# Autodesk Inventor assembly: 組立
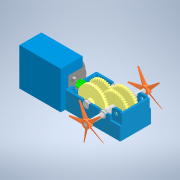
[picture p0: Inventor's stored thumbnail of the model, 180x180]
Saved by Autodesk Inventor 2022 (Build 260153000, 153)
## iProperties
Created: 2024-12
Part Number: 組立
Document SubType Name: Assembly
Designer: jsat7
Author: jsat7
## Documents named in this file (17)
- C:\Users\jsat7\OneDrive\デスクトップ\卒論2024\３DCAD\自在ギヤボックス\組立図\組立　低速.iam
- C:\Users\jsat7\OneDrive\デスクトップ\卒論2024\３DCAD\自在ギヤボックス\部品図\ボックス　下.ipt
- C:\Users\jsat7\OneDrive\デスクトップ\卒論2024\３DCAD\自在ギヤボックス\部品図\B3.ipt
- C:\Users\jsat7\OneDrive\デスクトップ\卒論2024\３DCAD\自在ギヤボックス\部品図\2段平ギア.iam
- C:\Users\jsat7\OneDrive\デスクトップ\卒論2024\３DCAD\自在ギヤボックス\部品図\B4.ipt
- C:\Users\jsat7\OneDrive\デスクトップ\卒論2024\３DCAD\自在ギヤボックス\部品図\B6.ipt
- C:\Users\jsat7\OneDrive\デスクトップ\卒論2024\３DCAD\自在ギヤボックス\部品図\丸棒.ipt
- C:\Users\jsat7\OneDrive\デスクトップ\卒論2024\３DCAD\自在ギヤボックス\部品図\クラウンギア.iam
- C:\Users\jsat7\OneDrive\デスクトップ\卒論2024\３DCAD\自在ギヤボックス\部品図\モーター　ピニオンギア.iam
- C:\Users\jsat7\OneDrive\デスクトップ\卒論2024\３DCAD\自在ギヤボックス\部品図\モーター　箱.ipt
- C:\Users\jsat7\OneDrive\デスクトップ\卒論2024\３DCAD\自在ギヤボックス\部品図\ピニオンギア.ipt
- C:\Users\jsat7\OneDrive\デスクトップ\卒論2024\３DCAD\自在ギヤボックス\部品図\特殊平ギア.ipt
- C:\Users\jsat7\OneDrive\デスクトップ\卒論2024\３DCAD\自在ギヤボックス\部品図\六角シャフト.ipt
- C:\Users\jsat7\OneDrive\デスクトップ\卒論2024\３DCAD\自在ギヤボックス\部品図\固定器具.ipt
- C:\Users\jsat7\OneDrive\デスクトップ\卒論2024\３DCAD\自在ギヤボックス\部品図\B7.ipt
- C:\Users\jsat7\OneDrive\デスクトップ\卒論2024\３DCAD\自在ギヤボックス\部品図\ボックス　上.ipt
- C:\Users\jsat7\OneDrive\デスクトップ\卒論2024\３DCAD\自在ギヤボックス\部品図\プロペラ.ipt
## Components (15 placed, 12 different names)
1. B4:1 — メイト:2, フラッシュ:2, メイト:3
2. B6:1 — メイト:1, メイト:28, メイト:29, フラッシュ:13
3. 丸棒:1 — メイト:3, メイト:5, メイト:20, メイト:28
4. クラウンギア:1 [sub-assembly] — メイト:5, メイト:22, 回転:1, 回転:2, メイト:29
5. モーター　ピニオンギア:1 [sub-assembly] — フラッシュ:5, フラッシュ:6, メイト:13, メイト:14, フラッシュ:8
6. 平歯車1:1 — メイト:14, フラッシュ:8, 回転:1, 角度:1
7. 平歯車1:2 — リジッド:1, メイト:23, 回転:4
8. 六角シャフト:1 — リジッド:1, リジッド:2, メイト:21, メイト:26, リジッド:3, リジッド:4
9. 固定器具:1 — リジッド:2, メイト:27
10. 2段平ギア:1 [sub-assembly] — メイト:20, メイト:22, 回転:3, 回転:4
11. 2段平ギア:2 [sub-assembly] — メイト:21, メイト:23, 回転:2, 回転:3
12. B3:1 — メイト:24, フラッシュ:11
13. B7:1 — メイト:25, フラッシュ:12, メイト:26, メイト:27
14. プロペラ:1 — リジッド:3
15. プロペラ:2 — リジッド:4
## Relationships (32: Mate 16, Flush 7, WeldJoint 4, RelateRotation 4, Angle 1)
- メイト:1 [Mate]: B6:1
- メイト:2 [Mate]: B4:1
- フラッシュ:2 [Flush]: B4:1
- メイト:3 [Mate]: B4:1 ↔ 丸棒:1
- メイト:5 [Mate]: 丸棒:1 ↔ クラウンギア:1
- フラッシュ:5 [Flush]: モーター　ピニオンギア:1
- フラッシュ:6 [Flush]: モーター　ピニオンギア:1
- メイト:13 [Mate]: モーター　ピニオンギア:1
- メイト:14 [Mate]: モーター　ピニオンギア:1 ↔ 平歯車1:1
- フラッシュ:8 [Flush]: モーター　ピニオンギア:1 ↔ 平歯車1:1
- リジッド:1 [WeldJoint]: 平歯車1:2 ↔ 六角シャフト:1
- リジッド:2 [WeldJoint]: 六角シャフト:1 ↔ 固定器具:1
- メイト:20 [Mate]: 丸棒:1 ↔ 2段平ギア:1
- メイト:21 [Mate]: 六角シャフト:1 ↔ 2段平ギア:2
- メイト:22 [Mate]: クラウンギア:1 ↔ 2段平ギア:1
- メイト:23 [Mate]: 平歯車1:2 ↔ 2段平ギア:2
- 回転:1 [RelateRotation]: クラウンギア:1 ↔ 平歯車1:1
- 回転:2 [RelateRotation]: クラウンギア:1 ↔ 2段平ギア:2
- 回転:3 [RelateRotation]: 2段平ギア:1 ↔ 2段平ギア:2
- 回転:4 [RelateRotation]: 平歯車1:2 ↔ 2段平ギア:1
- 角度:1 [Angle]: 平歯車1:1
- メイト:24 [Mate]: B3:1
- フラッシュ:11 [Flush]: B3:1
- メイト:25 [Mate]: B7:1
- フラッシュ:12 [Flush]: B7:1
- メイト:26 [Mate]: 六角シャフト:1 ↔ B7:1
- メイト:27 [Mate]: 固定器具:1 ↔ B7:1
- メイト:28 [Mate]: B6:1 ↔ 丸棒:1
- メイト:29 [Mate]: B6:1 ↔ クラウンギア:1
- フラッシュ:13 [Flush]: B6:1
- リジッド:3 [WeldJoint]: 六角シャフト:1 ↔ プロペラ:1
- リジッド:4 [WeldJoint]: 六角シャフト:1 ↔ プロペラ:2
